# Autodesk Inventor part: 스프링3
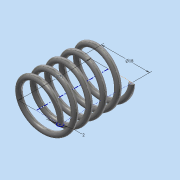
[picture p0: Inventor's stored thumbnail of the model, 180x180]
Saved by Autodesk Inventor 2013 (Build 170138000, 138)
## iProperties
Created: 2016-10
Part Number: 스프링3
Material: 강철, 탄소
Document SubType Name: Modeling
Designer: user
Mass: 6.88075 g
Surface Area: 17.7314 cm^2
Volume: 0.874302 cm^3
Density: 7.87 g/cm^3
Author: user
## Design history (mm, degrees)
sketch "스케치1"
  geometry: L1 (0, 0)-(9, 0); L2 (9, 0)-(9, 16.67); L3 (9, 16.67)-(0, 16.67); L4 (0, 16.67)-(0, 0); C1 r 1 at (9, 0)
  constraints: 8 end point, 2 parallel, 1 centre point, 1 coincident, 1 horizontal, 1 perpendicular
  dimensions: "d0" = 16.66987 distance of L3.end L1.start (derived); "d1" = 18 diameter of L2 L4; "d2" = 2 diameter of C1
feature "코일1" pitch "d3" = 10; turns "d5" = 5; dims "d4" = 16.66987 (= d0), "d6" = 0, angle "d7" = 90 deg, angle "d8" = 90 deg, "d9" = 0, "d10" = 0
sketch "스케치2"
  geometry: L1 (-8, 0)-(-10, 0) reference; 1 further point
  constraints: 1 horizontal alignment
extrude "돌출1" cut sketch "스케치2" distance "d11" = 10; taper "d12" = 0 deg
node "작업 평면1"
sketch "스케치3"
  geometry: L1 (-1, 0)-(1, 0) reference; 1 further point
  constraints: 1 horizontal alignment
extrude "돌출2" cut sketch "스케치3" distance "d14" = 10; taper "d15" = 0 deg
node "솔리드1"
node "절단 모서리 투영1"
node "절단 모서리 투영2"
other parameters: "d13" = 0
